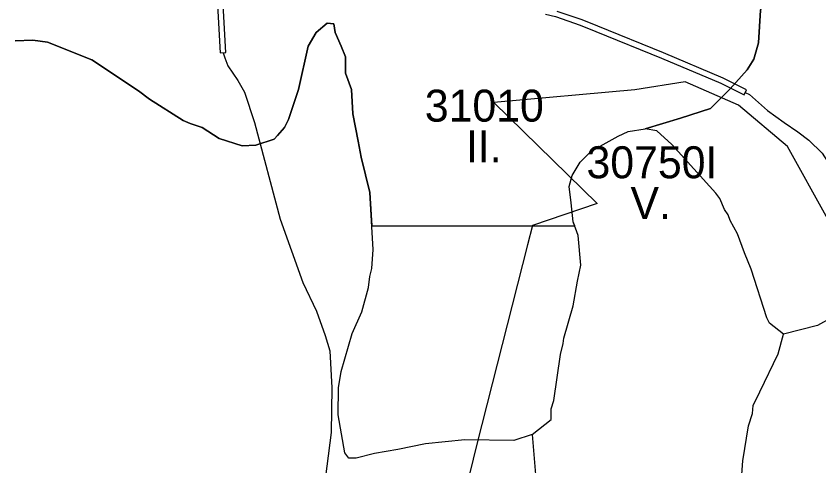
# Model space of a CAD drawing. Extents: x -555509 to -553014, y -1186753 to -1182560.
# Drawn here: x -554443 to -553941, y -1186033 to -1185751 of the extents above; entities that cross this region are included whole.
import ezdxf

# ---------------------------------------------------------------- set-up
doc = ezdxf.new("R2010")
doc.units = 0
for name, color, linetype in [('LEG_6_ZPF', 7, 'Continuous'), ('Level 29', 7, 'Continuous'), ('Level 41', 7, 'Continuous'), ('pěší_tr', 7, 'Continuous')]:
    doc.layers.add(name, color=color, linetype=linetype)

msp = doc.modelspace()

# ---------------------------------------------------------------- linework, layer by layer
at = {"layer": 'LEG_6_ZPF'}
msp.add_line((-554220.32, -1185882.32), (-554093.47, -1185882.32), dxfattribs=at)
for points in [[(-554049.38, -1185821.63), (-554027.38, -1185814.88), (-554008.69, -1185808.88), (-554003.19, -1185803.38), (-553996.38, -1185796.62), (-553985.81, -1185784.75), (-553981.56, -1185778), (-553978.62, -1185767.75), (-553977.31, -1185747.38), (-553974.38, -1185737.25), (-553971.38, -1185733.88), (-553963.75, -1185728.75), (-553952.75, -1185718.62), (-553947.62, -1185708.38), (-553945.94, -1185701.63), (-553945.12, -1185676.63)], [(-554443.25, -1185766.5), (-554432.25, -1185766.13), (-554422.94, -1185767.38), (-554395.38, -1185778.38), (-554366.12, -1185797.88), (-554359.31, -1185803), (-554338.12, -1185816.5), (-554333.88, -1185818.25), (-554326.25, -1185820.75), (-554315.69, -1185827.63), (-554301.25, -1185832.25), (-554292.75, -1185831.75), (-554281.31, -1185828), (-554279.19, -1185825.88), (-554274.94, -1185820.75), (-554272.44, -1185815.75), (-554266.06, -1185797), (-554260.12, -1185769.88), (-554255.06, -1185761.38), (-554248.25, -1185755.5), (-554244, -1185755.88), (-554243.19, -1185761.38), (-554239.38, -1185769.88), (-554236.81, -1185776.62), (-554236.81, -1185786.88), (-554233, -1185797), (-554232.12, -1185812.25), (-554228.75, -1185829.25), (-554227.06, -1185839.38), (-554221.56, -1185861.5), (-554220.32, -1185882.32)], [(-554093.47, -1185882.32), (-554094.38, -1185879.75), (-554095.62, -1185867.88), (-554096.88, -1185857.62), (-554095.19, -1185850.88), (-554090.12, -1185842.38), (-554083.31, -1185835.63), (-554066.38, -1185826.25), (-554060, -1185823.38), (-554049.38, -1185821.63)]]:
    msp.add_lwpolyline(points, dxfattribs=at)
at = {"layer": 'Level 29'}
for points in [[(-553945.12, -1185676.63), (-553945.94, -1185701.63), (-553947.62, -1185708.38), (-553952.75, -1185718.62), (-553963.75, -1185728.75), (-553971.38, -1185733.88), (-553974.38, -1185737.25), (-553977.31, -1185747.38), (-553978.62, -1185767.75), (-553981.56, -1185778), (-553985.81, -1185784.75), (-553996.38, -1185796.62), (-554003.19, -1185803.38), (-554008.69, -1185808.88), (-554027.38, -1185814.88), (-554049.38, -1185821.63)], [(-554120.19, -1186012.88), (-554131.62, -1186016.63), (-554162.19, -1186016.25), (-554186.75, -1186018.75), (-554204.12, -1186022.12), (-554218.56, -1186024.75), (-554230, -1186027.62), (-554234.69, -1186027.62), (-554237.25, -1186024.25), (-554241.44, -1186000.5), (-554241.06, -1185983.63), (-554239.38, -1185973.38), (-554232.56, -1185949.62), (-554226.62, -1185936.13), (-554222.38, -1185920.88), (-554221.56, -1185914), (-554220.25, -1185909), (-554219.44, -1185897.12), (-554221.56, -1185861.5), (-554227.06, -1185839.38), (-554228.75, -1185829.25), (-554232.12, -1185812.25), (-554233, -1185797), (-554236.81, -1185786.88), (-554236.81, -1185776.62), (-554239.38, -1185769.88), (-554243.19, -1185761.38), (-554244, -1185755.88), (-554248.25, -1185755.5), (-554255.06, -1185761.38), (-554260.12, -1185769.88), (-554266.06, -1185797), (-554272.44, -1185815.75), (-554274.94, -1185820.75), (-554279.19, -1185825.88), (-554281.31, -1185828), (-554292.75, -1185831.75), (-554301.25, -1185832.25), (-554315.69, -1185827.63), (-554326.25, -1185820.75), (-554333.88, -1185818.25), (-554338.12, -1185816.5), (-554359.31, -1185803), (-554366.12, -1185797.88), (-554395.38, -1185778.38), (-554422.94, -1185767.38), (-554432.25, -1185766.13), (-554443.25, -1185766.5)], [(-554120.19, -1186012.88), (-554108.31, -1186003.5), (-554108.31, -1185996.75), (-554106.62, -1185991.63), (-554102.38, -1185962.75), (-554100.69, -1185956), (-554100.25, -1185952.63), (-554094.38, -1185932.25), (-554091.81, -1185917), (-554089.69, -1185906.88), (-554091.38, -1185888.25), (-554094.38, -1185879.75), (-554095.62, -1185867.88), (-554096.88, -1185857.62), (-554095.19, -1185850.88), (-554090.12, -1185842.38), (-554083.31, -1185835.63), (-554066.38, -1185826.25), (-554060, -1185823.38), (-554049.38, -1185821.63)], [(-553962.94, -1185950.12), (-553971.81, -1185943.25), (-553973.5, -1185939.88), (-553983.25, -1185909.38), (-553987.5, -1185899.25), (-553991.75, -1185887.38), (-553996.38, -1185878.88), (-553997.69, -1185875.5), (-553999.81, -1185872.13), (-554002.75, -1185865.25), (-554005.31, -1185861.88), (-554032.88, -1185831.38), (-554042.19, -1185822.88), (-554049.38, -1185821.63)], [(-553931.94, -1185939.13), (-553941.69, -1185944.63), (-553962.94, -1185950.12)], [(-553942.56, -1186154.5), (-553945.5, -1186149.75), (-553957, -1186134.5), (-553960.38, -1186127.75), (-553966.31, -1186117.63), (-553976.88, -1186095.5), (-553978.19, -1186090.38), (-553979.88, -1186085.38), (-553988.75, -1186058.25), (-553989.62, -1186046.38), (-553988.38, -1186029.38), (-553984.94, -1186007.38), (-553982.44, -1185999.75), (-553982, -1185994.62), (-553977.75, -1185986.12), (-553966.31, -1185962.38), (-553962.94, -1185950.12)], [(-554120.19, -1186012.88), (-554118.06, -1186037.88), (-554118.5, -1186043), (-554117.69, -1186054.88), (-554113, -1186071.75), (-554107.5, -1186085.38), (-554101.12, -1186104), (-554095.62, -1186115.88), (-554084.19, -1186132.88), (-554071.88, -1186148.12), (-554056.19, -1186166.75), (-554044.75, -1186182), (-554037.94, -1186195.63), (-554032, -1186210.88)]]:
    msp.add_lwpolyline(points, dxfattribs=at)
at = {"layer": 'Level 41'}
msp.add_lwpolyline([(-554182.98, -1186256.1), (-554155.47, -1186273.1), (-554123.11, -1186282.01), (-554072.14, -1186285.25), (-554038.97, -1186290.1), (-553977.48, -1186303.05), (-553963.73, -1186269.87), (-553952.4, -1186214.01), (-553941.07, -1186171.92), (-553908.71, -1186067.5), (-553889.29, -1185995.46), (-553903.05, -1185979.27), (-553917.61, -1185938.8), (-553935.41, -1185878.09), (-553960.49, -1185832.76), (-553991.23, -1185806.85), (-554024.41, -1185792.28), (-554055.96, -1185797.14), (-554144.15, -1185805.24), (-554079.42, -1185868.37), (-554119.88, -1185882.13), (-554123.11, -1185894.28), (-554154.67, -1186018.93), (-554200.78, -1186207.54)], dxfattribs=at)
at = {"layer": 'pěší_tr'}
for points in [[(-554316.88, -1185740.24), (-554314.98, -1185774.09), (-554311.49, -1185773.9), (-554313.39, -1185740.09)], [(-554111.78, -1185749.93), (-554105.57, -1185751.45), (-554090.09, -1185756.69), (-554080.39, -1185760.64), (-554039.32, -1185777.34), (-554002.11, -1185793.01), (-553987.67, -1185800.4), (-553986.08, -1185797.29), (-554000.63, -1185789.84), (-554037.98, -1185774.1), (-554079.07, -1185757.4), (-554088.87, -1185753.41), (-554104.45, -1185748.13)], [(-554313.23, -1185774), (-554312.12, -1185777.24)], [(-554312.12, -1185777.24), (-554310.24, -1185782.31), (-554304.09, -1185791.3), (-554299.88, -1185798.7), (-554293.62, -1185817.63), (-554277.68, -1185878.08), (-554263.34, -1185917.81), (-554254.91, -1185935.57), (-554249.45, -1185950.83), (-554246.6, -1185960.51), (-554245.23, -1185983.62), (-554245.69, -1186011.51), (-554250.36, -1186047.26)], [(-553986.88, -1185798.85), (-553984.26, -1185800.08), (-553973.06, -1185810.19), (-553962.71, -1185817.58)], [(-553962.71, -1185817.58), (-553954.01, -1185823.48), (-553947.23, -1185828.75), (-553938.8, -1185836.91), (-553931.88, -1185847.87), (-553928.8, -1185855.33), (-553925.65, -1185876.03), (-553921.4, -1185904.94), (-553916.61, -1185927.54), (-553914, -1185941.79), (-553908.25, -1185954.4), (-553893.72, -1185976.74), (-553884.54, -1185988.38), (-553874.13, -1185998.52), (-553859.88, -1186007.02), (-553839.46, -1186016.61), (-553825.35, -1186021.54), (-553818.22, -1186022.36), (-553809.45, -1186020.31), (-553802.06, -1186016.61)]]:
    msp.add_lwpolyline(points, dxfattribs=at)

# ---------------------------------------------------------------- texts
at = {"layer": 'Level 29'}
for s, p in [('31010', (-554187.18, -1185817.11)), ('II.', (-554161.51, -1185842.56)), ('30750I', (-554086.13, -1185852.54)), ('V.', (-554058.64, -1185877.99))]:
    msp.add_text(s, height=20, dxfattribs=at).set_placement(p)

doc.saveas('drawing.dxf')
